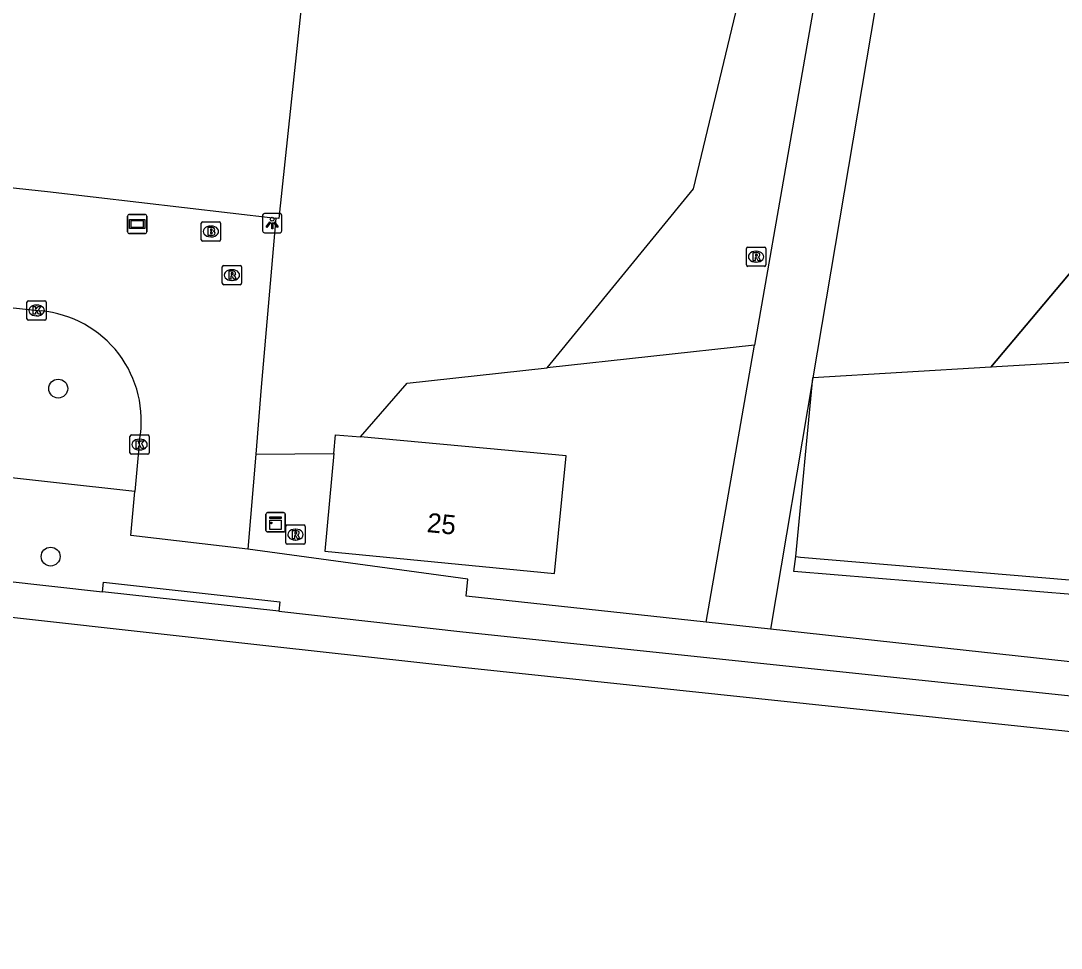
# Model space of a CAD drawing. Extents: x 162515 to 163909, y 388494 to 389773.
# Drawn here: x 163046.5 to 163100.4, y 388522.4 to 388570.5 of the extents above; entities that cross this region are included whole.
import ezdxf

# ---------------------------------------------------------------- set-up
doc = ezdxf.new("R2010")
doc.units = 0
for name, color, linetype in [('IMGEO_Boom', 7, 'Continuous'), ('IMGEO_Brandkraan', 7, 'Continuous'), ('IMGEO_Grasland_overig', 7, 'Continuous'), ('IMGEO_Groenvoorziening', 7, 'Continuous'), ('IMGEO_Haag', 7, 'Continuous'), ('IMGEO_Hek', 7, 'Continuous'), ('IMGEO_Kast', 7, 'Continuous'), ('IMGEO_Kolk', 7, 'Continuous'), ('IMGEO_Lichtpunt', 7, 'Continuous'), ('IMGEO_Loofbos', 7, 'Continuous'), ('IMGEO_Pand', 7, 'Continuous'), ('IMGEO_Pand_nummerreeks', 7, 'Continuous'), ('IMGEO_Rijbaan_lokaal_gesloten', 7, 'Continuous'), ('IMGEO_Rijbaan_lokaal_open', 7, 'Continuous'), ('IMGEO_Rioolput', 7, 'Continuous'), ('IMGEO_Verklikker', 7, 'Continuous'), ('IMGEO_Voetpad_open', 7, 'Continuous')]:
    doc.layers.add(name, color=color, linetype=linetype)

msp = doc.modelspace()

# ---------------------------------------------------------------- linework, layer by layer
at = {"layer": 'IMGEO_Boom'}
for centre in [(163048.454, 388551.441), (163048.061, 388542.734)]:
    msp.add_circle(centre, 0.489, dxfattribs=at)
at = {"layer": 'IMGEO_Brandkraan'}
for p, q in [((163055.863, 388559.157), (163055.863, 388560.009)), ((163055.938, 388560.083), (163056.79, 388560.083)), ((163056.351, 388559.863), (163056.376, 388559.863)), ((163056.864, 388560.009), (163056.864, 388559.157)), ((163056.374, 388559.303), (163056.349, 388559.303)), ((163056.79, 388559.083), (163055.938, 388559.083))]:
    msp.add_line(p, q, dxfattribs=at)
for points in [[(163055.863, 388559.157), (163055.863, 388560.009)], [(163055.938, 388560.083), (163056.79, 388560.083)], [(163056.211, 388559.783), (163056.211, 388559.383), (163056.424, 388559.383)], [(163056.442, 388559.783), (163056.211, 388559.783)], [(163056.39, 388559.702), (163056.336, 388559.702), (163056.336, 388559.626)], [(163056.864, 388560.009), (163056.864, 388559.157)], [(163056.336, 388559.626), (163056.389, 388559.626)], [(163056.398, 388559.55), (163056.336, 388559.55), (163056.336, 388559.469)], [(163056.336, 388559.469), (163056.398, 388559.469)], [(163056.79, 388559.083), (163055.938, 388559.083)]]:
    msp.add_lwpolyline(points, dxfattribs=at)
for centre, radius, start, end in [((163055.94, 388560.007), 0.0765, 91.552, 178.448), ((163055.94, 388560.007), 0.0765, 91.552, 178.448), ((163056.391, 388559.664), 0.0379, 267.8285, 90.9355), ((163056.446, 388559.638), 0.145, 59.4692, 91.5367), ((163056.471, 388559.685), 0.0922, 285.5137, 58.1501), ((163056.788, 388560.007), 0.0765, 1.552, 88.448), ((163056.788, 388560.007), 0.0765, 1.552, 88.448), ((163055.94, 388559.159), 0.0765, 181.552, 268.448), ((163055.94, 388559.159), 0.0765, 181.552, 268.448), ((163056.399, 388559.509), 0.0404, 269.8759, 90.5077), ((163056.43, 388559.634), 0.251, 268.6676, 293.5347), ((163056.476, 388559.493), 0.105, 301.3115, 78.989), ((163056.788, 388559.159), 0.0765, 271.552, 358.448), ((163056.788, 388559.159), 0.0765, 271.552, 358.448)]:
    msp.add_arc(centre, radius, start, end, dxfattribs=at)
for centre, major_axis, ratio, start_param, end_param in [((163056.35, 388559.583), (-0.387, 0.002), 0.722429, 4.712389, 7.853982), ((163056.375, 388559.583), (-0.39, 0.002), 0.717154, 1.570796, 4.712389)]:
    msp.add_ellipse(centre, major_axis=major_axis, ratio=ratio, start_param=start_param, end_param=end_param, dxfattribs=at)
at = {"layer": 'IMGEO_Grasland_overig'}
for points in [[(163094.191, 388609.039), (163084.529, 388553.697)], [(163082.024, 388539.339), (163084.529, 388553.697)], [(163087.55, 388552.001), (163085.355, 388538.977)], [(163086.667, 388542.733), (163087.55, 388552.001)]]:
    msp.add_lwpolyline(points, dxfattribs=at)
at = {"layer": 'IMGEO_Groenvoorziening'}
msp.add_lwpolyline([(163084.529, 388553.697), (163073.787, 388552.522)], dxfattribs=at)
at = {"layer": 'IMGEO_Haag'}
for points in [[(163086.667, 388542.733), (163086.905, 388542.71), (163117.864, 388540.098), (163165.007, 388536.066), (163165.881, 388543.752), (163165.291, 388544.507), (163165.822, 388544.867)], [(163160.875, 388535.356), (163156.823, 388535.834), (163126.891, 388538.502), (163111.633, 388539.893), (163086.571, 388541.959), (163086.667, 388542.733)]]:
    msp.add_lwpolyline(points, dxfattribs=at)
at = {"layer": 'IMGEO_Hek'}
msp.add_lwpolyline([(163096.774, 388552.545), (163150.202, 388616.103)], dxfattribs=at)
at = {"layer": 'IMGEO_Kast'}
for p, q in [((163059.217, 388544.087), (163059.217, 388544.928)), ((163059.217, 388544.928), (163059.217, 388544.087)), ((163059.292, 388545.012), (163060.133, 388545.012)), ((163060.133, 388545.012), (163059.292, 388545.012)), ((163060.217, 388544.937), (163060.217, 388544.096)), ((163060.217, 388544.096), (163060.217, 388544.937)), ((163060.142, 388544.012), (163059.301, 388544.012)), ((163059.301, 388544.012), (163060.142, 388544.012))]:
    msp.add_line(p, q, dxfattribs=at)
for points in [[(163059.412, 388544.802), (163060.012, 388544.802), (163060.012, 388544.717), (163059.412, 388544.717), (163059.412, 388544.802)], [(163059.412, 388544.627), (163060.012, 388544.627), (163060.012, 388544.138), (163059.412, 388544.138), (163059.412, 388544.627)]]:
    msp.add_lwpolyline(points, dxfattribs=at)
msp.add_circle((163059.496, 388544.476), 0.0377, dxfattribs=at)
for centre, start, end in [((163059.295, 388544.934), 92.4484, 184.2845), ((163059.295, 388544.934), 92.4484, 184.2845), ((163060.139, 388544.934), 2.4484, 94.2845), ((163060.139, 388544.934), 2.4484, 94.2845), ((163059.295, 388544.09), 182.4484, 274.2845), ((163059.295, 388544.09), 182.4484, 274.2845), ((163060.139, 388544.09), 272.4484, 4.2845), ((163060.139, 388544.09), 272.4484, 4.2845)]:
    msp.add_arc(centre, 0.0779, start, end, dxfattribs=at)
at = {"layer": 'IMGEO_Kolk'}
for p, q in [((163046.833, 388555.063), (163046.833, 388555.915)), ((163046.908, 388555.989), (163047.76, 388555.989)), ((163047.834, 388555.915), (163047.834, 388555.063)), ((163047.321, 388555.769), (163047.346, 388555.769)), ((163047.76, 388554.989), (163046.908, 388554.989)), ((163047.344, 388555.209), (163047.319, 388555.209)), ((163052.168, 388548.112), (163052.168, 388548.964)), ((163052.243, 388549.038), (163053.095, 388549.038)), ((163053.169, 388548.964), (163053.169, 388548.112)), ((163052.656, 388548.818), (163052.681, 388548.818)), ((163053.095, 388548.038), (163052.243, 388548.038)), ((163052.679, 388548.258), (163052.654, 388548.258))]:
    msp.add_line(p, q, dxfattribs=at)
for points in [[(163046.833, 388555.063), (163046.833, 388555.915)], [(163046.908, 388555.989), (163047.76, 388555.989)], [(163047.834, 388555.915), (163047.834, 388555.063)], [(163047.154, 388555.689), (163047.277, 388555.689), (163047.277, 388555.538), (163047.407, 388555.689), (163047.571, 388555.689), (163047.425, 388555.538), (163047.578, 388555.289), (163047.426, 388555.289), (163047.341, 388555.453), (163047.277, 388555.386), (163047.277, 388555.289), (163047.154, 388555.289), (163047.154, 388555.689)], [(163047.76, 388554.989), (163046.908, 388554.989)], [(163052.168, 388548.112), (163052.168, 388548.964)], [(163052.243, 388549.038), (163053.095, 388549.038)], [(163053.169, 388548.964), (163053.169, 388548.112)], [(163052.489, 388548.738), (163052.612, 388548.738), (163052.612, 388548.587), (163052.742, 388548.738), (163052.906, 388548.738), (163052.76, 388548.587), (163052.913, 388548.338), (163052.761, 388548.338), (163052.676, 388548.502), (163052.612, 388548.435), (163052.612, 388548.338), (163052.489, 388548.338), (163052.489, 388548.738)], [(163053.095, 388548.038), (163052.243, 388548.038)]]:
    msp.add_lwpolyline(points, dxfattribs=at)
for centre, start, end in [((163046.91, 388555.913), 91.552, 178.448), ((163046.91, 388555.913), 91.552, 178.448), ((163047.758, 388555.913), 1.552, 88.448), ((163047.758, 388555.913), 1.552, 88.448), ((163046.91, 388555.065), 181.552, 268.448), ((163046.91, 388555.065), 181.552, 268.448), ((163047.758, 388555.065), 271.552, 358.448), ((163047.758, 388555.065), 271.552, 358.448), ((163052.245, 388548.962), 91.552, 178.448), ((163052.245, 388548.962), 91.552, 178.448), ((163053.093, 388548.962), 1.552, 88.448), ((163053.093, 388548.962), 1.552, 88.448), ((163052.245, 388548.114), 181.552, 268.448), ((163052.245, 388548.114), 181.552, 268.448), ((163053.093, 388548.114), 271.552, 358.448), ((163053.093, 388548.114), 271.552, 358.448)]:
    msp.add_arc(centre, 0.0765, start, end, dxfattribs=at)
for centre, major_axis, ratio, start_param, end_param in [((163047.32, 388555.489), (-0.387, 0.002), 0.722429, 4.712389, 7.853982), ((163047.345, 388555.489), (-0.39, 0.002), 0.717154, 1.570796, 4.712389), ((163052.655, 388548.538), (-0.387, 0.002), 0.722429, 4.712389, 7.853982), ((163052.68, 388548.538), (-0.39, 0.002), 0.717154, 1.570796, 4.712389)]:
    msp.add_ellipse(centre, major_axis=major_axis, ratio=ratio, start_param=start_param, end_param=end_param, dxfattribs=at)
at = {"layer": 'IMGEO_Lichtpunt'}
for p, q in [((163059.042, 388560.419), (163059.042, 388559.612)), ((163059.042, 388560.419), (163059.042, 388559.612)), ((163059.944, 388560.514), (163059.136, 388560.514)), ((163059.944, 388560.514), (163059.136, 388560.514)), ((163060.038, 388559.612), (163060.038, 388560.419)), ((163060.038, 388559.612), (163060.038, 388560.419)), ((163059.136, 388559.518), (163059.944, 388559.518)), ((163059.136, 388559.518), (163059.944, 388559.518))]:
    msp.add_line(p, q, dxfattribs=at)
for points in [[(163059.416, 388560.083), (163059.455, 388560.055), (163059.267, 388559.793), (163059.229, 388559.82), (163059.416, 388560.083)], [(163059.518, 388560.035), (163059.565, 388560.035), (163059.565, 388559.713), (163059.518, 388559.713), (163059.518, 388560.035)], [(163059.628, 388560.055), (163059.666, 388560.082), (163059.853, 388559.82), (163059.814, 388559.792), (163059.628, 388560.055)]]:
    msp.add_lwpolyline(points, dxfattribs=at)
msp.add_circle((163059.541, 388560.217), 0.0994, dxfattribs=at)
for centre, start, end in [((163059.136, 388560.419), 90, 180), ((163059.136, 388560.419), 90, 180), ((163059.944, 388560.419), 0, 90), ((163059.944, 388560.419), 0, 90), ((163059.136, 388559.612), 180, 270), ((163059.136, 388559.612), 180, 270), ((163059.944, 388559.612), 270, 0), ((163059.944, 388559.612), 270, 360)]:
    msp.add_arc(centre, 0.0946, start, end, dxfattribs=at)
at = {"layer": 'IMGEO_Loofbos'}
for points in [[(163150.202, 388616.103), (163096.774, 388552.545)], [(163150.202, 388616.103), (163145.502, 388605.218), (163139.466, 388592.856), (163124.276, 388574.27), (163108.523, 388553.238), (163096.774, 388552.545)], [(163097.25, 388609.539), (163087.55, 388552.001)], [(163073.787, 388552.522), (163081.363, 388561.787), (163092.645, 388608.787)], [(163062.194, 388581.971), (163061.781, 388578.223), (163059.885, 388560.257), (163059.732, 388560.275)], [(163064.108, 388548.932), (163066.529, 388551.728), (163073.787, 388552.522)], [(163096.774, 388552.545), (163087.55, 388552.001)], [(163058.687, 388548.039), (163062.729, 388548.079)]]:
    msp.add_lwpolyline(points, dxfattribs=at)
at = {"layer": 'IMGEO_Pand'}
for points in [[(163062.729, 388548.079), (163062.262, 388543.01), (163074.17, 388541.859), (163074.775, 388547.956), (163064.108, 388548.932)], [(163062.729, 388548.079), (163062.818, 388549.05), (163064.108, 388548.932)]]:
    msp.add_lwpolyline(points, dxfattribs=at)
at = {"layer": 'IMGEO_Rijbaan_lokaal_gesloten'}
for points in [[(162908.963, 388554.88), (162948.321, 388550.488), (162948.369, 388550.483), (162964.579, 388548.669), (162987.025, 388546.161), (163014.762, 388543.071), (163031.566, 388541.204), (163040.29, 388540.234), (163059.674, 388538.08), (163069.219, 388537.019), (163114.004, 388532.296), (163131.035, 388530.402), (163175.638, 388525.237), (163176.288, 388525.112), (163177.403, 388524.656), (163178.09, 388524.156), (163178.758, 388523.432), (163178.982, 388523.125)], [(163040.394, 388542.064), (163050.754, 388540.913)], [(163059.876, 388539.899), (163050.754, 388540.913)], [(163059.876, 388539.899), (163069.421, 388538.838), (163114.206, 388534.115), (163174.485, 388527.411), (163175.154, 388527.297), (163175.927, 388527.098), (163176.68, 388526.831), (163177.406, 388526.497), (163178.099, 388526.1), (163178.754, 388525.643), (163179.365, 388525.129), (163179.929, 388524.562), (163180.439, 388523.948), (163180.892, 388523.29), (163181.189, 388522.764), (163181.189, 388522.764)]]:
    msp.add_lwpolyline(points, dxfattribs=at)
at = {"layer": 'IMGEO_Rijbaan_lokaal_open'}
for points in [[(162999.987, 388560.86), (163000.607, 388566.496), (163012.283, 388565.224), (163023.98, 388563.913), (163024.016, 388564.261), (163035.984, 388562.926), (163047.901, 388561.655), (163059.732, 388560.275)], [(163059.732, 388560.275), (163058.971, 388551.511), (163058.687, 388548.039)], [(163018.69, 388558.618), (163047.561, 388555.463)], [(163052.668, 388548.774), (163052.421, 388546.115)], [(163058.687, 388548.039), (163058.285, 388543.112)], [(163058.285, 388543.112), (163052.208, 388543.83), (163052.421, 388546.115)]]:
    msp.add_lwpolyline(points, dxfattribs=at)
msp.add_arc((163047.05, 388549.778), 5.708, 349.8645, 84.8584, dxfattribs=at)
at = {"layer": 'IMGEO_Rioolput'}
for p, q in [((163084.109, 388557.85), (163084.109, 388558.702)), ((163084.184, 388558.776), (163085.036, 388558.776)), ((163085.11, 388558.702), (163085.11, 388557.85)), ((163084.597, 388558.556), (163084.622, 388558.556)), ((163056.951, 388556.897), (163056.951, 388557.749)), ((163057.026, 388557.823), (163057.878, 388557.823)), ((163057.439, 388557.603), (163057.464, 388557.603)), ((163057.952, 388557.749), (163057.952, 388556.897)), ((163085.036, 388557.776), (163084.184, 388557.776)), ((163084.62, 388557.996), (163084.595, 388557.996)), ((163057.462, 388557.043), (163057.437, 388557.043)), ((163057.878, 388556.823), (163057.026, 388556.823)), ((163060.245, 388543.447), (163060.245, 388544.299)), ((163060.32, 388544.373), (163061.172, 388544.373)), ((163060.733, 388544.153), (163060.758, 388544.153)), ((163061.246, 388544.299), (163061.246, 388543.447)), ((163060.756, 388543.593), (163060.731, 388543.593)), ((163061.172, 388543.373), (163060.32, 388543.373))]:
    msp.add_line(p, q, dxfattribs=at)
for points in [[(163084.109, 388557.85), (163084.109, 388558.702)], [(163084.184, 388558.776), (163085.036, 388558.776)], [(163085.11, 388558.702), (163085.11, 388557.85)], [(163084.698, 388558.474), (163084.446, 388558.476), (163084.446, 388558.076)], [(163084.446, 388558.076), (163084.57, 388558.076), (163084.57, 388558.238), (163084.581, 388558.238)], [(163084.624, 388558.395), (163084.57, 388558.395), (163084.57, 388558.314)], [(163084.57, 388558.314), (163084.622, 388558.314)], [(163084.628, 388558.209), (163084.699, 388558.076), (163084.839, 388558.076), (163084.774, 388558.202)], [(163056.951, 388556.897), (163056.951, 388557.749)], [(163057.026, 388557.823), (163057.878, 388557.823)], [(163057.54, 388557.521), (163057.288, 388557.523), (163057.288, 388557.123)], [(163057.952, 388557.749), (163057.952, 388556.897)], [(163085.036, 388557.776), (163084.184, 388557.776)], [(163057.288, 388557.123), (163057.412, 388557.123), (163057.412, 388557.285), (163057.423, 388557.285)], [(163057.466, 388557.442), (163057.412, 388557.442), (163057.412, 388557.361)], [(163057.412, 388557.361), (163057.464, 388557.361)], [(163057.47, 388557.256), (163057.541, 388557.123), (163057.681, 388557.123), (163057.616, 388557.249)], [(163057.878, 388556.823), (163057.026, 388556.823)], [(163060.245, 388543.447), (163060.245, 388544.299)], [(163060.32, 388544.373), (163061.172, 388544.373)], [(163060.834, 388544.071), (163060.582, 388544.073), (163060.582, 388543.673)], [(163061.246, 388544.299), (163061.246, 388543.447)], [(163060.582, 388543.673), (163060.706, 388543.673), (163060.706, 388543.835), (163060.717, 388543.835)], [(163060.76, 388543.992), (163060.706, 388543.992), (163060.706, 388543.911)], [(163060.706, 388543.911), (163060.758, 388543.911)], [(163060.764, 388543.806), (163060.835, 388543.673), (163060.975, 388543.673), (163060.91, 388543.799)], [(163061.172, 388543.373), (163060.32, 388543.373)]]:
    msp.add_lwpolyline(points, dxfattribs=at)
for centre, radius, start, end in [((163084.186, 388558.7), 0.0765, 91.552, 178.448), ((163084.186, 388558.7), 0.0765, 91.552, 178.448), ((163085.034, 388558.7), 0.0765, 1.552, 88.448), ((163085.034, 388558.7), 0.0765, 1.552, 88.448), ((163084.58, 388558.185), 0.0533, 26.0293, 88.6989), ((163084.606, 388558.503), 0.19, 274.7715, 282.9687), ((163084.63, 388558.299), 0.0964, 77.0061, 93.1865), ((163084.644, 388558.356), 0.0378, 276.6634, 79.6772), ((163084.697, 388558.364), 0.109, 350.3612, 89.416), ((163084.695, 388558.364), 0.112, 277.5842, 350.9817), ((163084.679, 388558.149), 0.108, 29.5134, 73.7905), ((163057.028, 388557.747), 0.0765, 91.552, 178.448), ((163057.028, 388557.747), 0.0765, 91.552, 178.448), ((163057.539, 388557.411), 0.109, 350.3612, 89.416), ((163057.876, 388557.747), 0.0765, 1.552, 88.448), ((163057.876, 388557.747), 0.0765, 1.552, 88.448), ((163084.186, 388557.852), 0.0765, 181.552, 268.448), ((163084.186, 388557.852), 0.0765, 181.552, 268.448), ((163085.034, 388557.852), 0.0765, 271.552, 358.448), ((163085.034, 388557.852), 0.0765, 271.552, 358.448), ((163057.422, 388557.232), 0.0533, 26.0293, 88.6989), ((163057.448, 388557.55), 0.19, 274.7715, 282.9687), ((163057.472, 388557.346), 0.0964, 77.0061, 93.1865), ((163057.486, 388557.403), 0.0378, 276.6634, 79.6772), ((163057.537, 388557.411), 0.112, 277.5842, 350.9817), ((163057.521, 388557.196), 0.108, 29.5134, 73.7905), ((163057.028, 388556.899), 0.0765, 181.552, 268.448), ((163057.028, 388556.899), 0.0765, 181.552, 268.448), ((163057.876, 388556.899), 0.0765, 271.552, 358.448), ((163057.876, 388556.899), 0.0765, 271.552, 358.448), ((163060.322, 388544.297), 0.0765, 91.552, 178.448), ((163060.322, 388544.297), 0.0765, 91.552, 178.448), ((163060.833, 388543.961), 0.109, 350.3612, 89.416), ((163061.17, 388544.297), 0.0765, 1.552, 88.448), ((163061.17, 388544.297), 0.0765, 1.552, 88.448), ((163060.716, 388543.782), 0.0533, 26.0293, 88.6989), ((163060.742, 388544.1), 0.19, 274.7715, 282.9687), ((163060.766, 388543.896), 0.0964, 77.0061, 93.1865), ((163060.78, 388543.953), 0.0378, 276.6634, 79.6772), ((163060.831, 388543.961), 0.112, 277.5842, 350.9817), ((163060.815, 388543.746), 0.108, 29.5134, 73.7905), ((163060.322, 388543.449), 0.0765, 181.552, 268.448), ((163060.322, 388543.449), 0.0765, 181.552, 268.448), ((163061.17, 388543.449), 0.0765, 271.552, 358.448), ((163061.17, 388543.449), 0.0765, 271.552, 358.448)]:
    msp.add_arc(centre, radius, start, end, dxfattribs=at)
for centre, major_axis, ratio, start_param, end_param in [((163084.596, 388558.276), (-0.387, 0.002), 0.722429, 4.712389, 7.853982), ((163084.621, 388558.276), (-0.39, 0.002), 0.717154, 1.570796, 4.712389), ((163057.438, 388557.323), (-0.387, 0.002), 0.722429, 4.712389, 7.853982), ((163057.463, 388557.323), (-0.39, 0.002), 0.717154, 1.570796, 4.712389), ((163060.732, 388543.873), (-0.387, 0.002), 0.722429, 4.712389, 7.853982), ((163060.757, 388543.873), (-0.39, 0.002), 0.717154, 1.570796, 4.712389)]:
    msp.add_ellipse(centre, major_axis=major_axis, ratio=ratio, start_param=start_param, end_param=end_param, dxfattribs=at)
at = {"layer": 'IMGEO_Verklikker'}
for p, q in [((163052.051, 388559.57), (163052.051, 388560.37)), ((163052.051, 388560.37), (163052.051, 388559.57)), ((163052.151, 388560.47), (163052.941, 388560.47)), ((163052.941, 388560.47), (163052.151, 388560.47)), ((163053.041, 388560.37), (163053.041, 388559.57)), ((163053.041, 388559.57), (163053.041, 388560.37)), ((163052.941, 388559.47), (163052.151, 388559.47)), ((163052.151, 388559.47), (163052.941, 388559.47))]:
    msp.add_line(p, q, dxfattribs=at)
for points in [[(163052.152, 388560.202), (163052.94, 388560.202), (163052.94, 388559.738), (163052.152, 388559.738), (163052.152, 388560.202)], [(163052.217, 388560.137), (163052.217, 388559.803), (163052.875, 388559.803), (163052.875, 388560.137), (163052.217, 388560.137)]]:
    msp.add_lwpolyline(points, dxfattribs=at)
for centre, start, end in [((163052.151, 388560.37), 90, 180), ((163052.151, 388560.37), 90, 180), ((163052.941, 388560.37), 0, 90), ((163052.941, 388560.37), 360, 90), ((163052.151, 388559.57), 180, 270), ((163052.151, 388559.57), 180, 270), ((163052.941, 388559.57), 270, 0), ((163052.941, 388559.57), 270, 0)]:
    msp.add_arc(centre, 0.1, start, end, dxfattribs=at)
at = {"layer": 'IMGEO_Voetpad_open'}
for points in [[(163052.421, 388546.115), (163026.503, 388548.968), (163004.856, 388551.379)], [(163082.024, 388539.339), (163069.595, 388540.692), (163069.677, 388541.561), (163058.285, 388543.112)], [(163050.754, 388540.913), (163050.808, 388541.407), (163059.93, 388540.394), (163059.876, 388539.899)], [(163085.355, 388538.977), (163082.024, 388539.339)], [(163183.156, 388522.441), (163182.991, 388522.828), (163182.522, 388523.729), (163182.105, 388524.475), (163181.569, 388525.292), (163180.939, 388526.002), (163180.247, 388526.653), (163179.5, 388527.239), (163178.704, 388527.756), (163177.864, 388528.2), (163176.989, 388528.567), (163176.084, 388528.854), (163175.157, 388529.06), (163174.517, 388529.152), (163166.114, 388530.083), (163165.14, 388530.191), (163163.569, 388530.366), (163163.352, 388530.39), (163114.509, 388535.804), (163085.355, 388538.977)]]:
    msp.add_lwpolyline(points, dxfattribs=at)

# ---------------------------------------------------------------- texts
at = {"layer": 'IMGEO_Pand_nummerreeks'}
msp.add_text('25', height=1, rotation=354.4767, dxfattribs=at).set_placement((163067.525, 388544.009))

doc.saveas('drawing.dxf')
